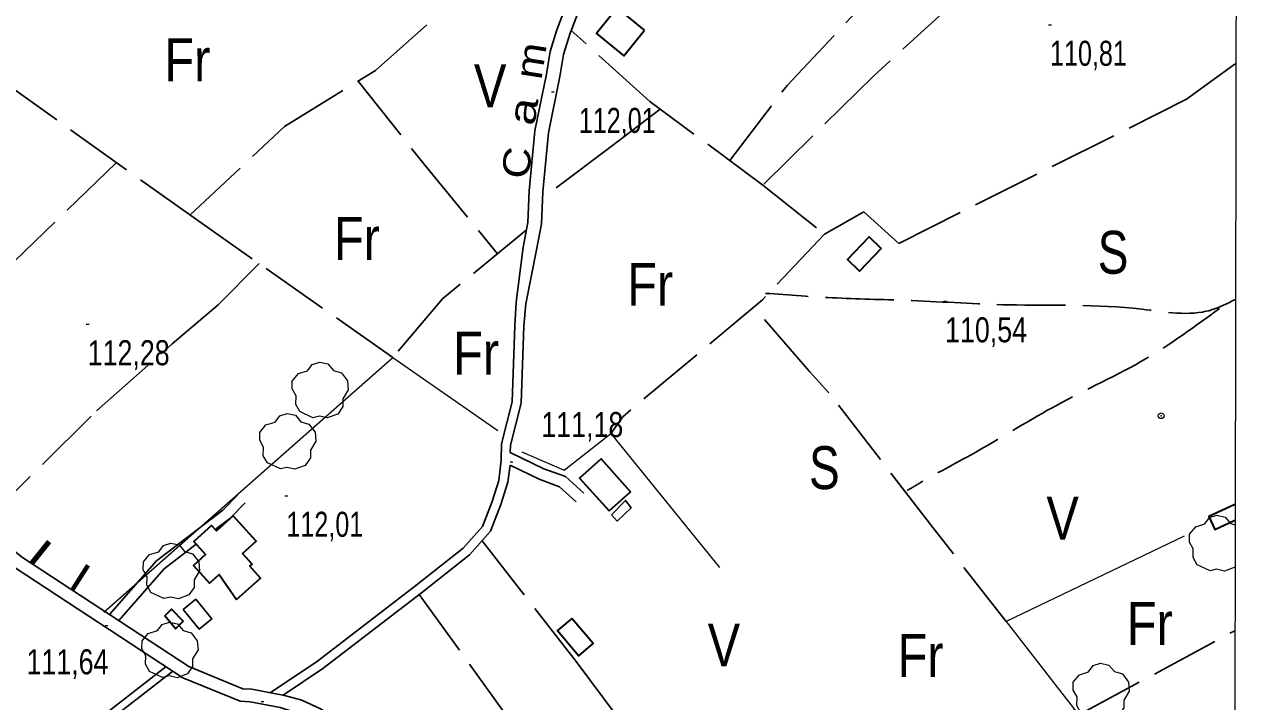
# Model space of a CAD drawing. Extents: x 483855 to 488461, y 4388206 to 4391419.
# Drawn here: x 487263.4 to 487689.7, y 4389040.8 to 4389277.5 of the extents above; entities that cross this region are included whole.
import ezdxf
from ezdxf.enums import TextEntityAlignment as Align

# ---------------------------------------------------------------- set-up
doc = ezdxf.new("R2010")
doc.units = 0
doc.header["$LTSCALE"] = 4
doc.header["$PDMODE"] = 32
doc.header["$PDSIZE"] = 2
doc.linetypes.add('LONG_DASHED', pattern=[7.5, 6, -1.5])
for name, color, linetype, lineweight in [('1', 7, 'Continuous', 13), ('21', 7, 'Continuous', 25), ('24', 7, 'Continuous', 13), ('25', 7, 'LONG_DASHED', 25), ('29', 7, 'Continuous', 13), ('36', 7, 'Continuous', 25), ('38', 7, 'Continuous', 25), ('47', 7, 'Continuous', 35), ('51', 7, 'Continuous', 13), ('7', 7, 'Continuous', 13), ('9', 7, 'Continuous', 13)]:
    doc.layers.add(name, color=color, linetype=linetype, lineweight=lineweight)
doc.layers.add('31', color=7, linetype='Continuous')
doc.layers.add('5', color=7, linetype='Continuous')

msp = doc.modelspace()

# ---------------------------------------------------------------- linework, layer by layer
at = {"layer": '1'}
msp.add_lwpolyline([(484115.5, 4391072.6), (487689.7, 4391065.7), (487685.8, 4388753.5), (484110.5, 4388760.3)], close=True, dxfattribs=at)
at = {"layer": '21'}
for points in [[(487468.54, 4389106.11), (487473.48, 4389111.08), (487475.36, 4389108.48), (487470.51, 4389103.88)], [(487318.89, 4389072.95), (487323.3, 4389076.57), (487328.94, 4389069.69), (487324.52, 4389066.07)]]:
    msp.add_lwpolyline(points, close=True, dxfattribs=at)
at = {"layer": '24'}
msp.add_lwpolyline([(487291.18, 4389072.03), (487392.1, 4389161.08), (487428.87, 4389135.51)], dxfattribs=at)
at = {"layer": '25'}
for p, q in [((487686.33, 4389263.55), (487686.66, 4389263.7)), ((487631.78, 4389036.14), (487686.01, 4389065.42)), ((487686.01, 4389065.42), (487686.33, 4389065.59))]:
    msp.add_line(p, q, dxfattribs=at)
for points in [[(487392.1, 4389161.08), (487323.51, 4389209.24), (487241.39, 4389268.03), (487214.61, 4389288.62), (487195.95, 4389309.51), (487173.95, 4389337.32), (487274.53, 4389416.03)], [(487509.89, 4389229.88), (487529.86, 4389256.14), (487570.39, 4389299.42), (487613.74, 4389347.66), (487633.92, 4389373.46), (487642.8, 4389374.51), (487656.66, 4389364.99), (487641.88, 4389353.67), (487649.27, 4389340.85)], [(487686.5, 4389370.29), (487654.5, 4389345.62), (487560.19, 4389259.55), (487521.45, 4389221.32), (487542.91, 4389204.18), (487556.69, 4389211.92), (487568.86, 4389200.95), (487669.37, 4389251.29), (487685.97, 4389263.39), (487686.33, 4389263.55)], [(487321.28, 4389210.85), (487354.29, 4389241.75), (487386.1, 4389261.4), (487428.33, 4389298.74)], [(487521.45, 4389221.32), (487481.93, 4389250.56), (487454.46, 4389275.38)], [(487380, 4389257.63), (487403.02, 4389228.69), (487428.69, 4389197.34)], [(487485.54, 4389247.9), (487468.38, 4389234.79), (487444.46, 4389216.77)], [(487295.56, 4389229.25), (487259.88, 4389194.62), (487225.77, 4389167.23), (487199.86, 4389138.58)], [(487438.84, 4389205.7), (487409.52, 4389181.55), (487392.1, 4389161.08)], [(487542.91, 4389204.18), (487521.3, 4389181.26), (487472.44, 4389140.37), (487468.31, 4389134.47)], [(487315.09, 4389165.79), (487331.13, 4389179.48), (487345.43, 4389193.86)], [(487544.46, 4389148.76), (487537.68, 4389156.14), (487518.23, 4389178.69)], [(487248.46, 4389102.54), (487288.6, 4389142.4), (487315.09, 4389165.79)], [(487606.45, 4389068.74), (487580.75, 4389101.6), (487544.46, 4389148.76)], [(487423.31, 4389097.02), (487456.17, 4389054.81), (487515.89, 4388974.24), (487630.41, 4389037.9)], [(487401.4, 4389078.24), (487437.03, 4389028.67), (487469.1, 4388989.72), (487488.55, 4388961.6), (487449.96, 4388939.98)]]:
    msp.add_lwpolyline(points, dxfattribs=at)
at = {"layer": '29'}
msp.add_line((487686.07, 4389102.64), (487686.39, 4389102.55), dxfattribs=at)
for points in [[(487364.2, 4389140.02), (487359.66, 4389142.14), (487358.25, 4389144.68), (487358.35, 4389147.66), (487356.98, 4389150.07), (487357.02, 4389152.82), (487359.18, 4389155.42), (487362.37, 4389156.42), (487364.02, 4389158.61), (487366.59, 4389159.44), (487369.45, 4389158.79), (487371.4, 4389156.52), (487374.21, 4389155.7), (487376.34, 4389152.85), (487376.58, 4389149.72), (487374.7, 4389146.57), (487374.7, 4389143.89), (487372.88, 4389141.28), (487369.26, 4389139.94), (487366.49, 4389140.57)], [(487352.85, 4389122.08), (487348.31, 4389124.2), (487346.9, 4389126.74), (487347, 4389129.72), (487345.63, 4389132.13), (487345.67, 4389134.88), (487347.83, 4389137.48), (487351.02, 4389138.48), (487352.67, 4389140.67), (487355.24, 4389141.5), (487358.1, 4389140.85), (487360.05, 4389138.58), (487362.86, 4389137.76), (487364.99, 4389134.91), (487365.23, 4389131.78), (487363.35, 4389128.63), (487363.35, 4389125.95), (487361.53, 4389123.34), (487357.91, 4389122), (487355.14, 4389122.63)], [(487312.2, 4389076.78), (487307.66, 4389078.9), (487306.25, 4389081.44), (487306.35, 4389084.42), (487304.98, 4389086.83), (487305.02, 4389089.58), (487307.18, 4389092.18), (487310.37, 4389093.18), (487312.02, 4389095.37), (487314.59, 4389096.2), (487317.45, 4389095.55), (487319.4, 4389093.28), (487322.21, 4389092.46), (487324.34, 4389089.61), (487324.58, 4389086.48), (487322.7, 4389083.33), (487322.7, 4389080.65), (487320.88, 4389078.04), (487317.26, 4389076.7), (487314.49, 4389077.33)], [(487311.71, 4389049.18), (487307.17, 4389051.3), (487305.76, 4389053.84), (487305.86, 4389056.82), (487304.49, 4389059.23), (487304.53, 4389061.98), (487306.69, 4389064.58), (487309.88, 4389065.58), (487311.53, 4389067.77), (487314.1, 4389068.6), (487316.96, 4389067.95), (487318.91, 4389065.68), (487321.72, 4389064.86), (487323.85, 4389062.01), (487324.09, 4389058.88), (487322.21, 4389055.73), (487322.21, 4389053.05), (487320.39, 4389050.44), (487316.77, 4389049.1), (487314, 4389049.73)], [(487637.03, 4389034.75), (487632.49, 4389036.87), (487631.08, 4389039.41), (487631.18, 4389042.39), (487629.81, 4389044.8), (487629.85, 4389047.55), (487632.01, 4389050.15), (487635.2, 4389051.15), (487636.85, 4389053.34), (487639.42, 4389054.17), (487642.28, 4389053.52), (487644.23, 4389051.25), (487647.04, 4389050.43), (487649.17, 4389047.58), (487649.41, 4389044.45), (487647.53, 4389041.3), (487647.53, 4389038.62), (487645.71, 4389036.01), (487642.09, 4389034.67), (487639.32, 4389035.3)]]:
    msp.add_lwpolyline(points, close=True, dxfattribs=at)
for points in [[(487677.63, 4389086.5), (487673.09, 4389088.62), (487671.68, 4389091.16), (487671.78, 4389094.14), (487670.41, 4389096.55), (487670.45, 4389099.3), (487672.61, 4389101.9), (487675.8, 4389102.9), (487677.45, 4389105.09), (487680.02, 4389105.92), (487682.88, 4389105.27), (487684.83, 4389103), (487686.07, 4389102.64)], [(487686.04, 4389087.66), (487682.69, 4389086.42), (487679.92, 4389087.05), (487677.63, 4389086.5)], [(487686.36, 4389087.84), (487686.31, 4389087.76), (487686.04, 4389087.66)]]:
    msp.add_lwpolyline(points, dxfattribs=at)
at = {"layer": '36'}
for points in [[(487056.6, 4389295.92), (487078.01, 4389257.02), (487097.75, 4389217.04), (487102.24, 4389208.07), (487114, 4389198.92), (487136.4, 4389180.47), (487168.83, 4389155.16), (487227.46, 4389113.49), (487260.17, 4389087.58), (487318.82, 4389049.13), (487338.77, 4389040.88), (487342.28, 4389040.64), (487352.75, 4389038.71), (487362.48, 4389035.58), (487369.58, 4389031.49), (487377.38, 4389024.86), (487396.67, 4388999.14), (487421.22, 4388970.66), (487442.04, 4388943.48), (487475.25, 4388896.39), (487489.91, 4388876.79), (487543.18, 4388805.78), (487581.31, 4388753.7)], [(487060.51, 4389298.04), (487081.96, 4389259.08), (487101.74, 4389219.02), (487105.77, 4389210.97), (487116.78, 4389202.39), (487139.19, 4389183.94), (487171.49, 4389158.73), (487230.13, 4389117.05), (487262.78, 4389091.19), (487320.9, 4389053.08), (487339.8, 4389045.27), (487342.84, 4389045.07), (487354.36, 4389042.94), (487360.31, 4389041.26), (487366.83, 4389038.24), (487374.29, 4389033.62), (487380.37, 4389028.3), (487400.14, 4389001.93), (487424.67, 4388973.47), (487445.62, 4388946.12), (487478.82, 4388899.05), (487507.99, 4388861.92), (487546.78, 4388808.4), (487586.82, 4388753.69)]]:
    msp.add_lwpolyline(points, dxfattribs=at)
at = {"layer": '38', "linetype": 'LONG_DASHED'}
msp.add_line((487686.52, 4389181.36), (487686.19, 4389181.22), dxfattribs=at)
at = {"layer": '38'}
for points in [[(487437.95, 4389172), (487438.57, 4389179.81), (487442.36, 4389198.69), (487444.1, 4389207.73), (487444.55, 4389218.98), (487446.51, 4389239.63), (487450.48, 4389259.26), (487451.73, 4389266.95), (487453.94, 4389274.01), (487462.72, 4389297.04), (487475.62, 4389328.43), (487493.2, 4389364.29), (487502.39, 4389382.97)], [(487434.78, 4389172.12), (487435.29, 4389180.45), (487437.67, 4389199.61), (487439.34, 4389208.28), (487439.79, 4389219.3), (487441.78, 4389240.33), (487445.78, 4389260.12), (487447.07, 4389268.05), (487449.42, 4389275.57), (487458.28, 4389298.8)], [(487349.33, 4389043.87), (487365.84, 4389054.92), (487400.22, 4389081.33), (487416.77, 4389094.41), (487423.5, 4389102.03), (487426.87, 4389110.72), (487429.17, 4389118.09), (487429.95, 4389125.12), (487430.1, 4389130.82), (487433.79, 4389145.51), (487434.78, 4389172.12)], [(487433.19, 4389127.83), (487433.26, 4389130.39), (487436.95, 4389145.06), (487437.95, 4389172)], [(487433.19, 4389127.83), (487444.85, 4389122.18), (487452.45, 4389119.4), (487458.9, 4389113.63)], [(487353.8, 4389043.04), (487367.69, 4389052.34), (487402.17, 4389078.83), (487418.96, 4389092.1), (487426.26, 4389100.35), (487429.87, 4389109.67), (487432.29, 4389117.44), (487433.09, 4389123.42)], [(487433.09, 4389123.42), (487443.28, 4389118.47), (487450.34, 4389115.89), (487456.21, 4389110.63)], [(487293.16, 4389071.27), (487309.59, 4389090), (487332.71, 4389107.71), (487337.87, 4389112.97)], [(487330.11, 4389100.89), (487335.25, 4389104.83), (487340.6, 4389110.29)], [(487296.4, 4389069.15), (487312.22, 4389087.19), (487323.46, 4389095.8)], [(487312.91, 4389053), (487288.23, 4389033.84), (487264.34, 4389015.11), (487226.01, 4388984), (487202.87, 4388965.7), (487186.58, 4388951.19), (487182.49, 4388943.72), (487179.46, 4388937.12), (487159.51, 4388919.94), (487141.9, 4388903.66), (487122.32, 4388889.25), (487115.8, 4388881.09)], [(487315.35, 4389051.41), (487289.92, 4389031.67), (487266.05, 4389012.96), (487227.73, 4388981.85), (487204.64, 4388963.59), (487188.76, 4388949.45), (487184.95, 4388942.48), (487181.71, 4388935.43), (487161.34, 4388917.89), (487149.49, 4388906.94)]]:
    msp.add_lwpolyline(points, dxfattribs=at)
at = {"layer": '38', "linetype": 'LONG_DASHED'}
for points in [[(487686.19, 4389181.22), (487677.87, 4389177.61), (487653.79, 4389177.94), (487607.17, 4389179.46), (487573.59, 4389180.94), (487547.21, 4389181.86), (487522.34, 4389183.48)], [(487680.89, 4389178.17), (487655.37, 4389160.72), (487624.18, 4389144.43), (487596.45, 4389128.35), (487576.5, 4389117.31), (487571.86, 4389114.58)]]:
    msp.add_spline(points, degree=3, dxfattribs=at)
at = {"layer": '47'}
for p, q in [((487686.4, 4389109.67), (487686.08, 4389109.52)), ((487686.07, 4389104.08), (487686.39, 4389104.23))]:
    msp.add_line(p, q, dxfattribs=at)
for points in [[(487480.1, 4389275.45), (487470.46, 4389283.23), (487463.26, 4389274.31), (487472.9, 4389266.53)], [(487562.74, 4389199.16), (487555.17, 4389191.22), (487550.93, 4389195.26), (487558.5, 4389203.2)], [(487467.68, 4389107.4), (487475.21, 4389114.13), (487464.93, 4389125.63), (487457.4, 4389118.9)], [(487337.59, 4389076.44), (487345.97, 4389083.88), (487342.19, 4389088.13), (487342.95, 4389088.81), (487339.64, 4389092.5), (487344.44, 4389096.82), (487336.42, 4389105.72), (487330.56, 4389100.44), (487328.8, 4389102.38), (487322.6, 4389096.76), (487326.72, 4389092.21), (487322.46, 4389088.36), (487328.09, 4389082.12), (487331.5, 4389085.19)], [(487312.46, 4389070.72), (487314.77, 4389073.06), (487318.94, 4389068.92), (487316.28, 4389066.25)], [(487454.69, 4389069.85), (487449.68, 4389065.62), (487457.13, 4389056.81), (487462.14, 4389061.04)]]:
    msp.add_lwpolyline(points, close=True, dxfattribs=at)
msp.add_lwpolyline([(487686.08, 4389109.52), (487677.26, 4389105.45), (487679.32, 4389100.97), (487686.07, 4389104.08)], dxfattribs=at)
at = {"layer": '51'}
for points in [[(487437.16, 4389128.09), (487451.99, 4389121.62), (487468.31, 4389134.47), (487506.25, 4389087.64)], [(487668.6, 4389098.55), (487606.45, 4389068.74), (487680.99, 4388972.78)]]:
    msp.add_lwpolyline(points, dxfattribs=at)
at = {"layer": '7'}
for p, q in [((487621.23, 4389277.37), (487622.23, 4389277.37)), ((487447.52, 4389253.93), (487448.52, 4389253.93)), ((487584.57, 4389180.72), (487585.57, 4389180.72)), ((487285.06, 4389172.72), (487286.06, 4389172.72)), ((487433.11, 4389124.58), (487434.11, 4389124.58)), ((487354.47, 4389112.75), (487355.47, 4389112.75)), ((487291.61, 4389067.43), (487292.61, 4389067.43)), ((487346.14, 4389040.87), (487347.14, 4389040.87))]:
    msp.add_line(p, q, dxfattribs=at)
at = {"layer": '9'}
msp.add_point((487660.55, 4389140.7), dxfattribs=at)

# ---------------------------------------------------------------- texts
at = {"layer": '31'}
for s, width, p in [('Fr', 0.85, (487320.36, 4389257.6)), ('V', 0.85, (487426.16, 4389248.47)), ('Fr', 0.85, (487379.6, 4389195.14)), ('S', 0.8, (487643.76, 4389190.33)), ('Fr', 0.85, (487482.06, 4389179.12)), ('Fr', 0.85, (487421.22, 4389155.09)), ('S', 0.8, (487542.9, 4389115.05)), ('V', 0.85, (487626.14, 4389097.43)), ('Fr', 0.85, (487656.56, 4389060.59)), ('V', 0.85, (487507.81, 4389053.06)), ('Fr', 0.85, (487576.51, 4389049.38))]:
    msp.add_text(s, height=15, dxfattribs=dict(at, width=width)).set_placement(p, align=Align.CENTER)
at = {"layer": '5'}
for s, rotation, width, p in [('m', 81.254, 1.2, (487445.01, 4389264.09)), ('a', 81.254, 1.35, (487442.31, 4389246.47)), ('C', 83.882, 1.2, (487440.18, 4389228.63)), ('l', 321.226, 1.65, (487265.83, 4389088.91)), ('l', 327.446, 1.4, (487280.3, 4389080.02))]:
    msp.add_text(s, height=9.49, rotation=rotation, dxfattribs=dict(at, width=width)).set_placement(p, align=Align.CENTER)
at = {"layer": '7'}
for s, width, p in [('110,81', 0.75, (487621.73, 4389263)), ('112,01', 0.75, (487457.12, 4389239.56)), ('110,54', 0.8, (487585.07, 4389166.35)), ('112,28', 0.8, (487285.56, 4389158.35)), ('111,18', 0.8, (487444.02, 4389133.22)), ('112,01', 0.75, (487354.97, 4389098.38)), ('111,64', 0.8, (487264.17, 4389050.32))]:
    msp.add_text(s, height=8.75, dxfattribs=dict(at, width=width)).set_placement(p)

doc.saveas('drawing.dxf')
